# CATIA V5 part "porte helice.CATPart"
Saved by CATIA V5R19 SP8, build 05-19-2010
Part number: porte helice
Bounding box of the stored display mesh (mm): x -20 to 20, y -50 to 180, z -20 to 20
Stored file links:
  G:\EU_thinkMotion\CFAO_2010\MMS_groupe2\MMS_groupe2\A reprendre\splanchenault\Planchenault\porte helice.CATPart
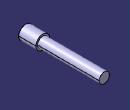
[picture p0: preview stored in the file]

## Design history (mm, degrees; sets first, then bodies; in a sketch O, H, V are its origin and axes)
Body1 (main body)
  Sketch1 on zx-plane, origin (0, 0, 0), H (-1, 0, 0), V (0, 0, 1)
    circle A1 centre (0, 0) radius 15
    radius A1 = 15
  Pad1: profile Sketch1, direction (0, 1, 0), length 180
  Sketch2 on start face of Pad1, origin (0, 0, 0), H (1, 0, 0), V (0, 0, 1)
    circle A1 centre (0, 0) radius 20
    radius A1 = 20
  Pad2: profile Sketch2, direction (0, -1, 0), length 50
